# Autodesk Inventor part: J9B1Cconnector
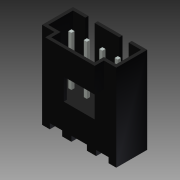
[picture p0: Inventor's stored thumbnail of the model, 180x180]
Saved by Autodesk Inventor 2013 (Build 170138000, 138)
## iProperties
Company: Autodesk Inc.
Created: 2005-12
Part Number: J9B1Cconnector
Document SubType Name: Modeling
Designer: Autodesk Inc.
Density: 1 g/cm^3
Mass: 0.404375 g
Surface Area: 8.9745 cm^2
Volume: 0.404375 cm^3
Material: Allgemein
Title: Personal Computer
Author: Autodesk Inc.
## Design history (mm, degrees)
sketch "Sketch1"
  geometry: L1 (0, 6.3)-(0, -2.8) reference; L2 (-8.4, 0)-(8.4, 0) reference; L3 (-6, 0)-(6, 0); L4 (6, 0)-(6, 5); L5 (6, 5)-(-6, 5); L6 (-6, 5)-(-6, 0); L7 (-4, 0)-(4, 0); L8 (4, 0)-(4, -1.5); L9 (4, -1.5)-(-4, -1.5); L10 (-4, -1.5)-(-4, 0)
  constraints: 16 end point, 4 parallel, 2 horizontal, 2 perpendicular, 2 point on line, 2 other
  dimensions: "d0" = 12 distance of L4.end L5.end; "d1" = 5 distance of L5.end L3.start; "d2" = 1.5 distance of L9.end L7.start; "d3" = 8 distance of L8.end L9.end
extrude "Extrusion1" new body sketch "Sketch1" distance "d4" = 14; taper "d5" = 0 deg
shell "Shell1" dims "d6" = 0.5, "d10" = 5
sketch "Sketch2"
  geometry: L1 (8, 0)-(8, 14) reference; L2 (0, 0)-(8, 0); L3 (8, 0)-(8, 10); L4 (8, 10)-(0, 10); L5 (0, 10)-(0, 0)
  constraints: 8 end point, 2 parallel, 1 horizontal, 1 perpendicular, 1 point on line
  dimensions: "d7" = 10 distance between parallel lines of L2 L4
extrude "Extrusion2" cut sketch "Sketch2" stored distance "d8" = 14; taper "d9" = 0 deg
sketch "Sketch3"
  geometry: L1 (0.5, 1.5)-(0.5, 2) reference; L2 (7.5, 2)-(7.5, 1.5) reference; L3 (0.5, 2)-(1.5, 2); L4 (1.5, 2)-(1.5, 1.5); L5 (1.5, 1.5)-(0.5, 1.5); L6 (0.5, 1.5)-(0.5, 2); L7 (7.5, 2)-(6.5, 2); L8 (6.5, 2)-(6.5, 1.5); L9 (6.5, 1.5)-(7.5, 1.5); L10 (7.5, 1.5)-(7.5, 2); L11 (-2, 1.5)-(10, 1.5) reference
  constraints: 16 end point, 4 parallel, 2 collinear, 2 horizontal, 2 perpendicular
  dimensions: "d11" = 1 distance of L1.end L3.end; "d12" = 1 distance of L2.start L7.end (= d11)
extrude "Extrusion3" join sketch "Sketch3" stored distance "d13" = 14; taper "d14" = 0 deg
sketch "Sketch4"
  geometry: L1 (-5.5, 4.5)-(5.5, 4.5) reference; L2 (-6, 5)-(6, 5) reference; L3 (0, 6.3)-(0, -2.8) reference; L4 (-3.5, 5)-(-2, 5); L5 (-2, 5)-(-2, 4.5); L6 (-2, 4.5)-(-3.5, 4.5); L7 (-3.5, 4.5)-(-3.5, 5); L8 (2, 5)-(3.5, 5); L9 (3.5, 5)-(3.5, 4.5); L10 (3.5, 4.5)-(2, 4.5); L11 (2, 4.5)-(2, 5)
  constraints: 16 end point, 4 parallel, 4 point on line, 2 horizontal, 2 perpendicular, 2 other
  dimensions: "d15" = 2 distance between parallel lines of L3 L5; "d16" = 1.5 distance between parallel lines of L7 L5
extrude "Extrusion4" cut sketch "Sketch4" stored distance "d17" = 14; taper "d18" = 0 deg
sketch "Sketch5"
  geometry: L1 (12, 0)-(0, 0) reference; L2 (6, 2.8)-(6, -16.8) reference; L3 (4.75, 0)-(7.25, 0); L4 (7.25, 0)-(7.25, -0.85); L5 (7.25, -0.85)-(4.75, -0.85); L6 (4.75, -0.85)-(4.75, 0); L7 (3.25, 0)-(1.25, 0); L8 (1.25, 0)-(1.25, -0.85); L9 (1.25, -0.85)-(3.25, -0.85); L10 (3.25, -0.85)-(3.25, 0); L11 (8.75, 0)-(10.75, 0); L12 (10.75, 0)-(10.75, -0.85); L13 (10.75, -0.85)-(8.75, -0.85); L14 (8.75, -0.85)-(8.75, 0)
  constraints: 24 end point, 6 parallel, 3 horizontal, 3 perpendicular, 3 point on line, 2 collinear, 3 other
  dimensions: "d19" = 2.5 distance of L4.end L5.end; "d20" = 2 distance of L8.end L9.end; "d21" = 1.5 distance between parallel lines of L6 L10; "d22" = 0.85 distance of L7.end L8.end
extrude "Extrusion5" cut sketch "Sketch5" stored distance "d23" = 14; taper "d24" = 0 deg
sketch "Sketch6"
  geometry: L1 (0, 0)-(0, 4) reference; L2 (-11, 4)-(-11, 0) reference; L3 (-5.5, 5.8)-(-5.5, -3.3) reference; L4 (-11, 2)-(0, 2); L5 (-4.5, 2.25)-(-4, 2.25); L6 (-4, 2.25)-(-4, 1.75); L7 (-4, 1.75)-(-4.5, 1.75); L8 (-4.5, 1.75)-(-4.5, 2.25); L9 (-2, 2.25)-(-1.5, 2.25); L10 (-1.5, 2.25)-(-1.5, 1.75); L11 (-1.5, 1.75)-(-2, 1.75); L12 (-2, 1.75)-(-2, 2.25); L13 (-6.5, 2.25)-(-7, 2.25); L14 (-7, 2.25)-(-7, 1.75); L15 (-7, 1.75)-(-6.5, 1.75); L16 (-6.5, 1.75)-(-6.5, 2.25); L17 (-9, 2.25)-(-9.5, 2.25); L18 (-9.5, 2.25)-(-9.5, 1.75); L19 (-9.5, 1.75)-(-9, 1.75); L20 (-9, 1.75)-(-9, 2.25)
  constraints: 34 end point, 8 parallel, 5 equal length, 4 horizontal, 4 perpendicular, 2 midpoint, 8 other
  dimensions: "d25" = 1 distance between parallel lines of L3 L16; "d26" = 0.5 distance of L13.start L13.end; "d27" = 2 distance between parallel lines of L14 L20
extrude "Extrusion6" join sketch "Sketch6" distance "d28" = 8; taper "d29" = 0 deg
body "Solid1"
